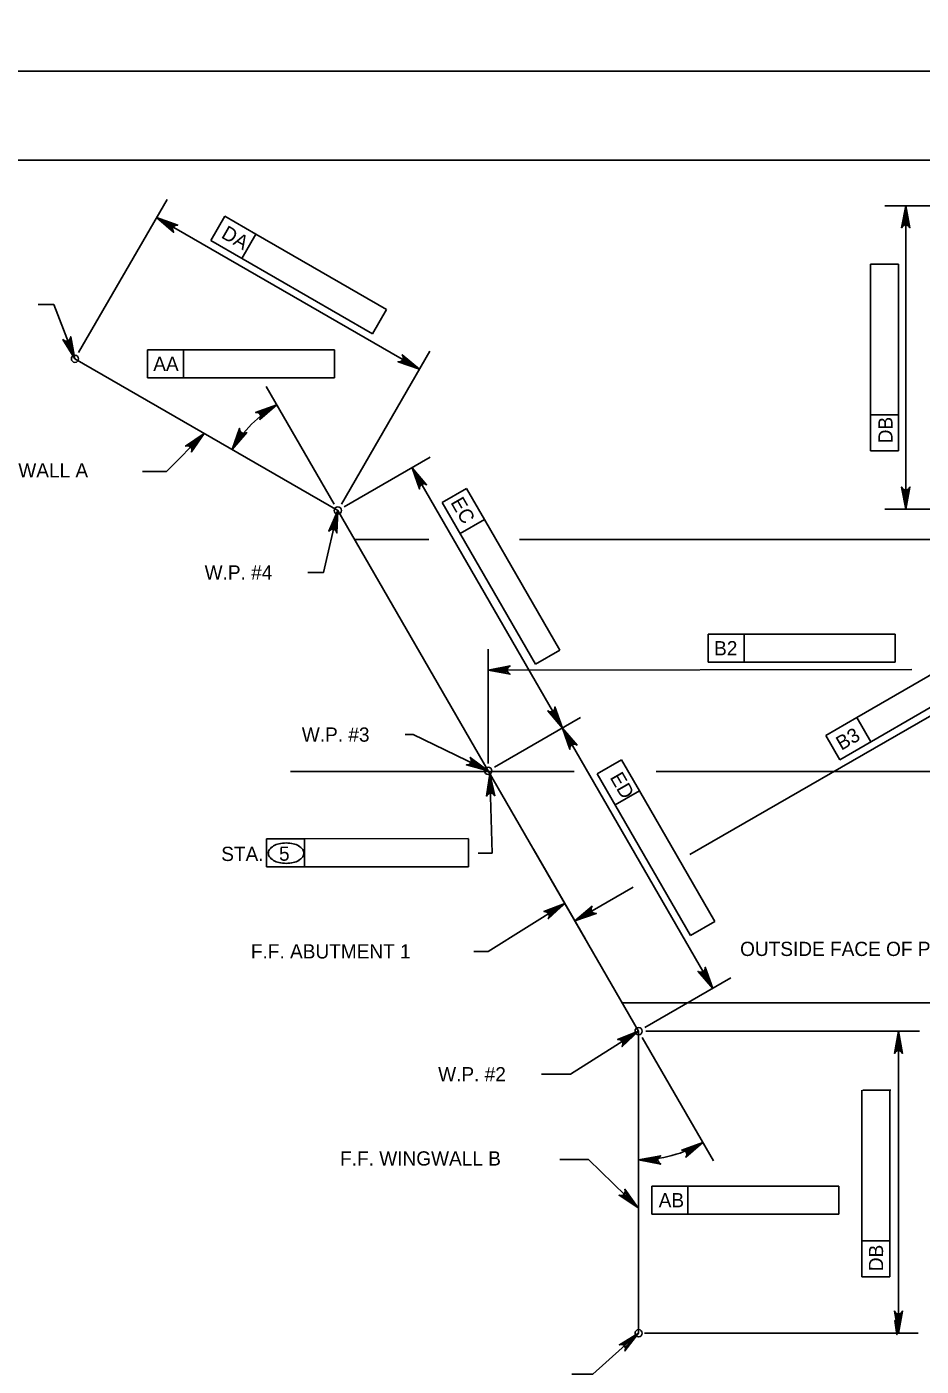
# Model space of a CAD drawing. Extents: x 0 to 36.3, y -66 to 0.
# Drawn here: x 16.33 to 23.87, y -32.92 to -21.62 of the extents above; entities that cross this region are included whole.
import ezdxf

# ---------------------------------------------------------------- set-up
doc = ezdxf.new("R2010")
doc.units = 0
for name, color, linetype in [('1', 7, 'Continuous'), ('2', 7, 'Continuous'), ('3', 7, 'Continuous'), ('4', 7, 'Continuous'), ('63', 7, 'Continuous')]:
    doc.layers.add(name, color=color, linetype=linetype)

msp = doc.modelspace()

# ---------------------------------------------------------------- linework, layer by layer
at = {"layer": '1'}
msp.add_lwpolyline([(1.75, -43.25), (33.25, -43.25), (33.25, -22.75), (1.75, -22.75)], close=True, dxfattribs=at)
at = {"layer": '2'}
for p, q in [((18.954, -25.704), (16.738, -24.424)), ((18.954, -25.704), (21.489, -30.094)), ((19.72, -25.947), (19.095, -25.947)), ((25.791, -25.947), (20.486, -25.947)), ((28.046, -29.854), (21.35, -29.854)), ((21.489, -30.094), (21.489, -32.64))]:
    msp.add_line(p, q, dxfattribs=at)
at = {"layer": '3'}
for p, q in [((20.945, -27.903), (18.556, -27.903)), ((28.894, -27.903), (21.637, -27.903))]:
    msp.add_line(p, q, dxfattribs=at)
for centre in [(16.738, -24.424), (18.954, -25.704), (20.221, -27.899), (21.489, -30.094), (21.489, -32.641)]:
    msp.add_circle(centre, 0.0304, dxfattribs=at)
at = {"layer": '4'}
for p, q in [((16.768, -24.371), (17.514, -23.08)), ((25.582, -23.134), (23.563, -23.134)), ((23.74, -23.134), (23.74, -25.693)), ((17.425, -23.234), (19.641, -24.513)), ((18, -23.222), (17.882, -23.427)), ((18, -23.222), (18.262, -23.373)), ((18.262, -23.373), (18.144, -23.578)), ((18.262, -23.373), (19.364, -24.009)), ((17.882, -23.427), (19.246, -24.214)), ((23.442, -23.626), (23.678, -23.626)), ((23.442, -24.898), (23.442, -23.626)), ((23.678, -25.201), (23.678, -23.626)), ((19.364, -24.009), (19.246, -24.214)), ((17.35, -24.349), (17.653, -24.349)), ((17.35, -24.349), (17.35, -24.586)), ((17.653, -24.349), (17.653, -24.586)), ((17.653, -24.349), (18.925, -24.349)), ((18.925, -24.349), (18.925, -24.586)), ((18.985, -25.651), (19.73, -24.36)), ((17.35, -24.586), (18.925, -24.586)), ((18.923, -25.651), (18.351, -24.659)), ((23.442, -25.201), (23.442, -24.898)), ((23.442, -24.898), (23.678, -24.898)), ((19.007, -25.673), (19.732, -25.255)), ((23.442, -25.201), (23.678, -25.201)), ((17.509, -25.375), (17.308, -25.375)), ((19.579, -25.343), (20.846, -27.538)), ((20.038, -25.518), (19.834, -25.636)), ((20.038, -25.518), (20.189, -25.78)), ((19.834, -25.636), (20.621, -27)), ((25.582, -25.693), (23.563, -25.693)), ((20.189, -25.78), (19.985, -25.898)), ((20.189, -25.78), (20.825, -26.882)), ((21.921, -28.605), (25.974, -26.265)), ((22.076, -26.746), (22.379, -26.746)), ((22.076, -26.746), (22.076, -26.983)), ((22.379, -26.746), (22.379, -26.983)), ((22.379, -26.746), (23.651, -26.746)), ((23.651, -26.746), (23.651, -26.983)), ((20.221, -27.838), (20.22, -26.872)), ((23.328, -27.449), (24.429, -26.813)), ((20.825, -26.882), (20.621, -27)), ((22.076, -26.983), (23.651, -26.983)), ((20.22, -27.05), (23.792, -27.044)), ((23.184, -27.805), (24.547, -27.017)), ((20.275, -27.868), (20.999, -27.45)), ((20.846, -27.538), (22.113, -29.734)), ((23.066, -27.6), (23.328, -27.449)), ((23.328, -27.449), (23.446, -27.653)), ((23.066, -27.6), (23.184, -27.805)), ((21.344, -27.805), (21.139, -27.923)), ((21.344, -27.805), (21.495, -28.067)), ((20.236, -27.924), (20.255, -28.592)), ((21.139, -27.923), (21.927, -29.287)), ((21.495, -28.067), (21.291, -28.185)), ((21.495, -28.067), (22.131, -29.169)), ((18.353, -28.472), (18.673, -28.472)), ((18.353, -28.709), (18.353, -28.472)), ((18.673, -28.472), (20.054, -28.47)), ((18.673, -28.707), (18.673, -28.471)), ((20.054, -28.471), (20.054, -28.707)), ((20.603, -28.56), (21.04, -29.318)), ((20.255, -28.592), (20.135, -28.592)), ((20.054, -28.707), (18.353, -28.709)), ((20.952, -29.164), (21.444, -28.88)), ((20.867, -29.017), (20.221, -29.421)), ((22.131, -29.169), (21.927, -29.287)), ((20.221, -29.421), (20.101, -29.421)), ((21.542, -30.064), (22.267, -29.645)), ((21.519, -30.148), (22.119, -31.187)), ((21.55, -30.095), (23.856, -30.095)), ((23.679, -30.095), (23.679, -32.641)), ((23.371, -32.164), (23.371, -30.59)), ((23.379, -30.591), (23.615, -30.591)), ((23.607, -32.166), (23.607, -30.591)), ((21.067, -31.175), (20.824, -31.175)), ((21.601, -31.401), (23.176, -31.401)), ((21.601, -31.401), (21.601, -31.637)), ((21.904, -31.401), (21.904, -31.637)), ((23.176, -31.401), (23.176, -31.637)), ((21.601, -31.637), (23.176, -31.637)), ((23.373, -31.862), (23.609, -31.863)), ((23.371, -32.166), (23.607, -32.166)), ((21.537, -32.641), (23.844, -32.641))]:
    msp.add_line(p, q, dxfattribs=at)
for points in [[(23.74, -23.134), (23.775, -23.32), (23.765, -23.306), (23.752, -23.299), (23.74, -23.296), (23.727, -23.299), (23.715, -23.306), (23.705, -23.32), (23.74, -23.134), (23.715, -23.306), (23.727, -23.299), (23.74, -23.134), (23.74, -23.296), (23.752, -23.299), (23.74, -23.134), (23.765, -23.306)], [(17.425, -23.234), (17.604, -23.297), (17.587, -23.298), (17.574, -23.305), (17.566, -23.315), (17.561, -23.327), (17.562, -23.341), (17.569, -23.357), (17.425, -23.234), (17.562, -23.341), (17.561, -23.327), (17.425, -23.234), (17.566, -23.315), (17.574, -23.305), (17.425, -23.234), (17.587, -23.298)], [(16.738, -24.424), (16.56, -23.968), (16.428, -23.968)], [(16.738, -24.424), (16.637, -24.263), (16.652, -24.273), (16.666, -24.276), (16.679, -24.273), (16.69, -24.267), (16.699, -24.255), (16.703, -24.238), (16.738, -24.424), (16.699, -24.255), (16.69, -24.267), (16.738, -24.424), (16.679, -24.273), (16.666, -24.276), (16.738, -24.424), (16.652, -24.273)], [(19.641, -24.513), (19.462, -24.45), (19.48, -24.449), (19.492, -24.442), (19.501, -24.432), (19.505, -24.42), (19.505, -24.406), (19.497, -24.39), (19.641, -24.513), (19.505, -24.406), (19.505, -24.42), (19.641, -24.513), (19.501, -24.432), (19.492, -24.442), (19.641, -24.513), (19.48, -24.449)], [(18.439, -24.813), (18.295, -24.936), (18.303, -24.92), (18.303, -24.906), (18.299, -24.894), (18.29, -24.884), (18.278, -24.877), (18.26, -24.876), (18.439, -24.813), (18.278, -24.877), (18.29, -24.884), (18.439, -24.813), (18.299, -24.894), (18.303, -24.906), (18.439, -24.813), (18.303, -24.92)], [(17.827, -25.053), (17.509, -25.375)], [(17.827, -25.053), (17.72, -25.21), (17.723, -25.193), (17.72, -25.179), (17.712, -25.169), (17.702, -25.162), (17.688, -25.158), (17.671, -25.161), (17.827, -25.053), (17.688, -25.158), (17.702, -25.162), (17.827, -25.053), (17.712, -25.169), (17.72, -25.179), (17.827, -25.053), (17.723, -25.193)], [(18.063, -25.189), (18.126, -25.011), (18.127, -25.028), (18.134, -25.041), (18.144, -25.049), (18.156, -25.053), (18.17, -25.053), (18.186, -25.046), (18.063, -25.189), (18.17, -25.053), (18.156, -25.053), (18.063, -25.189), (18.144, -25.049), (18.134, -25.041), (18.063, -25.189), (18.127, -25.028)], [(19.579, -25.343), (19.702, -25.487), (19.686, -25.48), (19.672, -25.48), (19.66, -25.484), (19.65, -25.492), (19.643, -25.505), (19.642, -25.522), (19.579, -25.343), (19.643, -25.505), (19.65, -25.492), (19.579, -25.343), (19.66, -25.484), (19.672, -25.48), (19.579, -25.343), (19.686, -25.48)], [(23.74, -25.693), (23.705, -25.506), (23.715, -25.521), (23.727, -25.528), (23.74, -25.53), (23.752, -25.528), (23.765, -25.521), (23.775, -25.506), (23.74, -25.693), (23.765, -25.521), (23.752, -25.528), (23.74, -25.693), (23.74, -25.53), (23.727, -25.528), (23.74, -25.693), (23.715, -25.521)], [(18.954, -25.704), (18.834, -26.226), (18.701, -26.226)], [(18.954, -25.704), (18.946, -25.893), (18.94, -25.877), (18.929, -25.867), (18.917, -25.862), (18.905, -25.862), (18.891, -25.866), (18.878, -25.878), (18.954, -25.704), (18.891, -25.866), (18.905, -25.862), (18.954, -25.704), (18.917, -25.862), (18.929, -25.867), (18.954, -25.704), (18.94, -25.877)], [(20.22, -27.05), (20.406, -27.014), (20.392, -27.024), (20.384, -27.037), (20.382, -27.049), (20.384, -27.062), (20.392, -27.074), (20.406, -27.084), (20.22, -27.05), (20.392, -27.074), (20.384, -27.062), (20.22, -27.05), (20.382, -27.049), (20.384, -27.037), (20.22, -27.05), (20.392, -27.024)], [(20.846, -27.538), (20.723, -27.394), (20.738, -27.402), (20.753, -27.402), (20.765, -27.398), (20.775, -27.39), (20.782, -27.377), (20.783, -27.36), (20.846, -27.538), (20.782, -27.377), (20.775, -27.39), (20.846, -27.538), (20.765, -27.398), (20.753, -27.402), (20.846, -27.538), (20.738, -27.402)], [(20.846, -27.538), (20.97, -27.682), (20.954, -27.675), (20.939, -27.675), (20.927, -27.679), (20.918, -27.687), (20.91, -27.7), (20.909, -27.717), (20.846, -27.538), (20.91, -27.7), (20.918, -27.687), (20.846, -27.538), (20.927, -27.679), (20.939, -27.675), (20.846, -27.538), (20.954, -27.675)], [(20.221, -27.899), (19.589, -27.593), (19.52, -27.593)], [(20.221, -27.899), (20.038, -27.849), (20.055, -27.847), (20.068, -27.839), (20.075, -27.828), (20.078, -27.816), (20.077, -27.802), (20.069, -27.786), (20.221, -27.899), (20.077, -27.802), (20.078, -27.816), (20.221, -27.899), (20.075, -27.828), (20.068, -27.839), (20.221, -27.899), (20.055, -27.847)], [(20.236, -27.924), (20.276, -28.109), (20.266, -28.095), (20.253, -28.088), (20.24, -28.086), (20.228, -28.089), (20.216, -28.097), (20.206, -28.111), (20.236, -27.924), (20.216, -28.097), (20.228, -28.089), (20.236, -27.924), (20.24, -28.086), (20.253, -28.088), (20.236, -27.924), (20.266, -28.095)], [(20.867, -29.017), (20.727, -29.146), (20.734, -29.13), (20.734, -29.115), (20.729, -29.103), (20.721, -29.094), (20.708, -29.087), (20.69, -29.086), (20.867, -29.017), (20.708, -29.087), (20.721, -29.094), (20.867, -29.017), (20.729, -29.103), (20.734, -29.115), (20.867, -29.017), (20.734, -29.13)], [(20.952, -29.164), (21.096, -29.041), (21.088, -29.057), (21.088, -29.071), (21.092, -29.083), (21.101, -29.093), (21.113, -29.1), (21.131, -29.101), (20.952, -29.164), (21.113, -29.1), (21.101, -29.093), (20.952, -29.164), (21.092, -29.083), (21.088, -29.071), (20.952, -29.164), (21.088, -29.057)], [(22.113, -29.734), (21.99, -29.59), (22.006, -29.597), (22.02, -29.597), (22.032, -29.593), (22.042, -29.585), (22.049, -29.572), (22.051, -29.555), (22.113, -29.734), (22.049, -29.572), (22.042, -29.585), (22.113, -29.734), (22.032, -29.593), (22.02, -29.597), (22.113, -29.734), (22.006, -29.597)], [(21.489, -30.094), (20.915, -30.457), (20.669, -30.457)], [(21.489, -30.094), (21.35, -30.224), (21.357, -30.207), (21.356, -30.193), (21.351, -30.181), (21.343, -30.172), (21.33, -30.165), (21.312, -30.165), (21.489, -30.094), (21.33, -30.165), (21.343, -30.172), (21.489, -30.094), (21.351, -30.181), (21.356, -30.193), (21.489, -30.094), (21.357, -30.207)], [(23.679, -30.095), (23.714, -30.281), (23.704, -30.267), (23.691, -30.259), (23.679, -30.257), (23.666, -30.259), (23.654, -30.267), (23.644, -30.281), (23.679, -30.095), (23.654, -30.267), (23.666, -30.259), (23.679, -30.095), (23.679, -30.257), (23.691, -30.259), (23.679, -30.095), (23.704, -30.267)], [(22.031, -31.034), (21.887, -31.157), (21.894, -31.141), (21.895, -31.127), (21.89, -31.115), (21.882, -31.105), (21.869, -31.098), (21.852, -31.096), (22.031, -31.034), (21.869, -31.098), (21.882, -31.105), (22.031, -31.034), (21.89, -31.115), (21.895, -31.127), (22.031, -31.034), (21.894, -31.141)], [(21.489, -31.179), (21.675, -31.144), (21.661, -31.154), (21.653, -31.166), (21.651, -31.179), (21.653, -31.191), (21.661, -31.204), (21.675, -31.214), (21.489, -31.179), (21.661, -31.204), (21.653, -31.191), (21.489, -31.179), (21.651, -31.179), (21.653, -31.166), (21.489, -31.179), (21.661, -31.154)], [(21.481, -31.582), (21.067, -31.175)], [(21.481, -31.582), (21.324, -31.477), (21.341, -31.48), (21.355, -31.476), (21.365, -31.468), (21.373, -31.458), (21.376, -31.444), (21.373, -31.427), (21.481, -31.582), (21.376, -31.444), (21.373, -31.458), (21.481, -31.582), (21.365, -31.468), (21.355, -31.476), (21.481, -31.582), (21.341, -31.48)], [(23.679, -32.641), (23.644, -32.454), (23.654, -32.469), (23.666, -32.476), (23.679, -32.478), (23.691, -32.476), (23.704, -32.469), (23.714, -32.454), (23.679, -32.641), (23.704, -32.469), (23.691, -32.476), (23.679, -32.641), (23.679, -32.478), (23.666, -32.476), (23.679, -32.641), (23.654, -32.469)], [(21.489, -32.64), (21.104, -32.985), (20.925, -32.985)], [(21.489, -32.64), (21.373, -32.79), (21.377, -32.773), (21.374, -32.759), (21.368, -32.748), (21.358, -32.74), (21.344, -32.736), (21.327, -32.738), (21.489, -32.64), (21.344, -32.736), (21.358, -32.74), (21.489, -32.64), (21.368, -32.748), (21.374, -32.759), (21.489, -32.64), (21.377, -32.773)]]:
    msp.add_lwpolyline(points, dxfattribs=at)
for points in [[(23.72, -23.252), (23.76, -23.252), (23.74, -23.134)], [(17.537, -23.276), (17.518, -23.31), (17.425, -23.234)], [(16.738, -24.424), (16.704, -24.311), (16.686, -24.318)], [(19.549, -24.437), (19.529, -24.471), (19.641, -24.513)], [(17.827, -25.053), (17.737, -25.13), (17.751, -25.144)], [(19.655, -25.436), (19.621, -25.455), (19.579, -25.343)], [(23.72, -25.575), (23.76, -25.575), (23.74, -25.693)], [(18.954, -25.704), (18.918, -25.817), (18.937, -25.821)], [(20.338, -27.03), (20.338, -27.069), (20.22, -27.05)], [(20.804, -27.426), (20.77, -27.446), (20.846, -27.538)], [(20.922, -27.631), (20.888, -27.651), (20.846, -27.538)], [(20.221, -27.899), (20.119, -27.839), (20.111, -27.857)], [(20.259, -28.044), (20.219, -28.046), (20.235, -27.925)], [(20.759, -29.108), (20.738, -29.074), (20.851, -29.027)], [(21.044, -29.088), (21.064, -29.122), (20.952, -29.164)], [(22.072, -29.621), (22.037, -29.641), (22.113, -29.734)], [(21.489, -30.094), (21.384, -30.149), (21.394, -30.166)], [(23.659, -30.223), (23.698, -30.224), (23.679, -30.105)], [(21.481, -31.582), (21.404, -31.493), (21.39, -31.507)], [(23.647, -32.533), (23.687, -32.534), (23.666, -32.652)], [(21.489, -32.64), (21.394, -32.711), (21.407, -32.726)]]:
    msp.add_lwpolyline(points, close=True, dxfattribs=at)
for centre, radius, start, end in [((18.954, -25.704), 1.029, 120.0001, 150.0006), ((18.419, -28.593), 0.0513, 144.1862, 180), ((18.466, -28.627), 0.109, 119.8571, 144.1862), ((18.497, -28.681), 0.172, 103.3749, 119.8571), ((18.518, -28.767), 0.26, 90, 103.3749), ((18.518, -28.767), 0.26, 76.6251, 90), ((18.538, -28.681), 0.172, 60.1429, 76.6251), ((18.569, -28.627), 0.109, 35.8138, 60.1429), ((18.616, -28.593), 0.0513, 0, 35.8138), ((18.419, -28.593), 0.0513, 180, 215.8138), ((18.466, -28.559), 0.109, 215.8138, 240.1429), ((18.497, -28.505), 0.172, 240.1429, 256.6251), ((18.518, -28.419), 0.26, 256.6251, 270), ((18.518, -28.419), 0.26, 270, 283.3749), ((18.538, -28.505), 0.172, 283.3749, 299.8571), ((18.569, -28.559), 0.109, 299.8571, 324.1862), ((18.616, -28.593), 0.0513, 324.1862, 0), ((21.489, -30.094), 1.085, 269.9998, 299.9996)]:
    msp.add_arc(centre, radius, start, end, dxfattribs=at)
at = {"layer": '63'}
for points in [[(0, -22), (34, -22), (34, 0), (0, 0)], [(0, -44), (34, -44), (34, -22), (0, -22)]]:
    msp.add_lwpolyline(points, close=True, dxfattribs=at)

# ---------------------------------------------------------------- texts
at = {"layer": '4'}
for s, rotation, p in [('DA', 330, (17.963, -23.399)), ('DB', 90, (23.629, -25.137)), ('EC', 300, (19.9, -25.635)), ('B3', 30, (23.197, -27.73)), ('ED', 300, (21.243, -27.954)), ('5', 0.0618, (18.458, -28.657)), ('DB', 89.7109, (23.549, -32.118))]:
    msp.add_text(s, height=0.12, rotation=rotation, dxfattribs=at).set_placement(p)
for s, p in [('AA', (17.398, -24.527)), ('F.F. WINGWALL A', (15.494, -25.425)), ('W.P. #4', (17.831, -26.286)), ('B2', (22.125, -26.925)), ('W.P. #3', (18.65, -27.653)), ('STA.', (17.971, -28.659)), ('F.F. ABUTMENT 1', (18.221, -29.481)), ('OUTSIDE FACE OF PARAPET (TYP.)', (22.344, -29.46)), ('W.P. #2', (19.799, -30.517)), ('F.F. WINGWALL B', (18.973, -31.227)), ('AB', (21.658, -31.579))]:
    msp.add_text(s, height=0.12, dxfattribs=at).set_placement(p)

doc.saveas('drawing.dxf')
